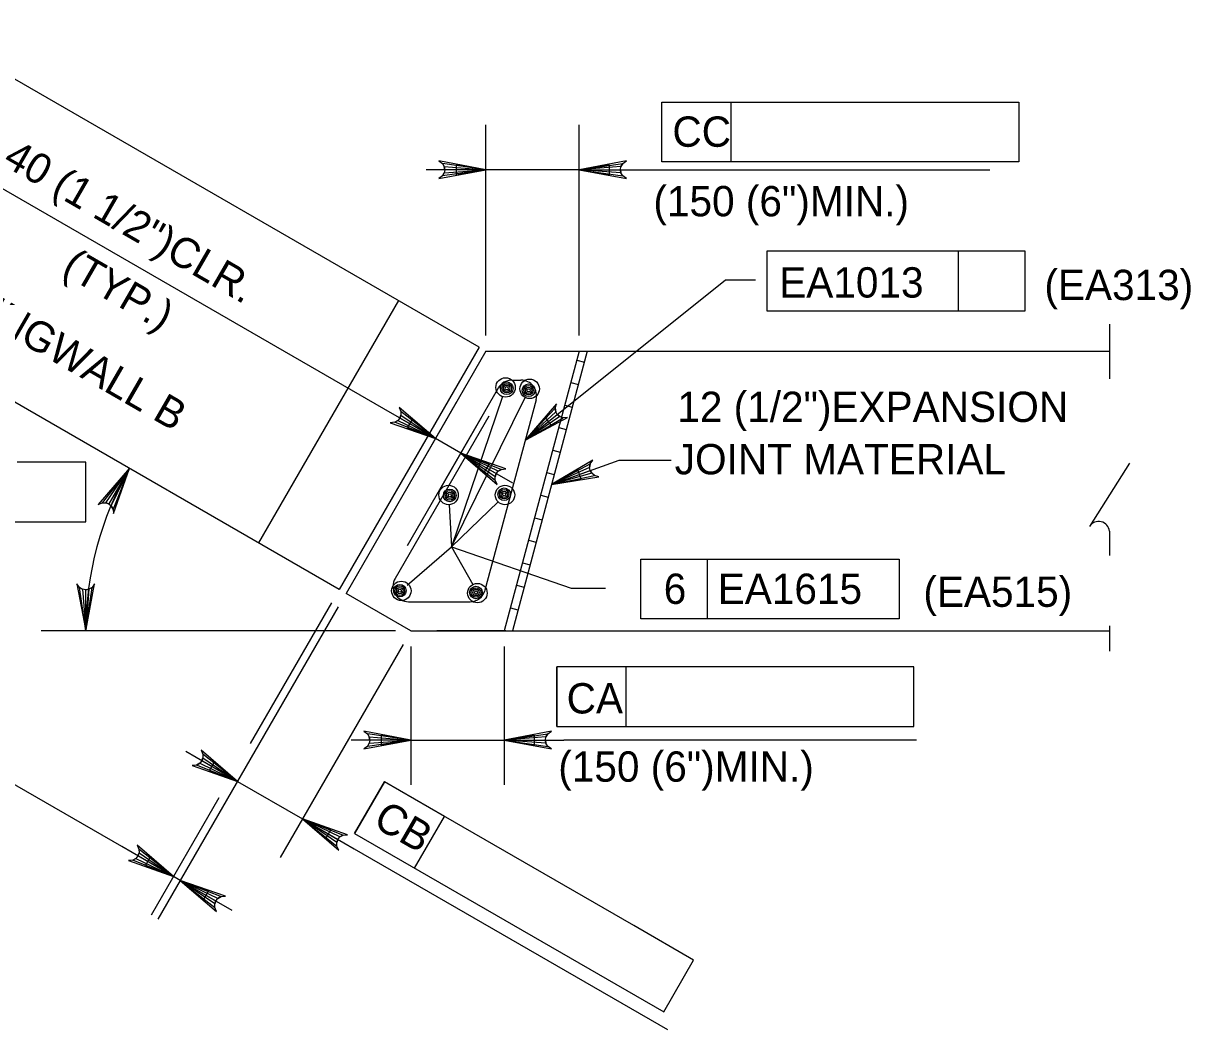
# Model space of a CAD drawing. Extents: x 638340 to 640241, y 295465 to 298435.
# Drawn here: x 638568.5 to 638683.9, y 296941.4 to 297041 of the extents above; entities that cross this region are included whole.
import ezdxf

# ---------------------------------------------------------------- set-up
doc = ezdxf.new("R2010")
doc.units = 0
for name, color, linetype in [('10', 7, 'Continuous'), ('3', 7, 'Continuous'), ('4', 7, 'Continuous'), ('5', 7, 'Continuous')]:
    doc.layers.add(name, color=color, linetype=linetype)

msp = doc.modelspace()

# ---------------------------------------------------------------- linework, layer by layer
at = {"layer": '10'}
for p, q in [((638613.57, 297008.95), (638558.08, 297040.99)), ((638599.73, 296984.98), (638544.23, 297017.02)), ((638605.58, 297013.57), (638591.74, 296989.59)), ((638613.57, 297008.95), (638599.73, 296984.98)), ((638614.24, 297008.57), (638600.4, 296984.59)), ((638614.24, 297008.57), (638675.9, 297008.57)), ((638623.47, 297008.57), (638616.05, 296980.88)), ((638624.26, 297008.57), (638616.85, 296980.88)), ((638623.23, 297007.68), (638623.97, 297007.48)), ((638622.63, 297005.45), (638623.38, 297005.25)), ((638622.04, 297003.22), (638622.78, 297003.02)), ((638621.44, 297001), (638622.18, 297000.8)), ((638620.84, 296998.77), (638621.58, 296998.57)), ((638620.24, 296996.54), (638620.99, 296996.34)), ((638619.65, 296994.31), (638620.39, 296994.11)), ((638619.05, 296992.08), (638619.79, 296991.88)), ((638618.45, 296989.85), (638619.2, 296989.65)), ((638617.85, 296987.63), (638618.6, 296987.43)), ((638617.26, 296985.4), (638618, 296985.2)), ((638606.82, 296980.88), (638600.4, 296984.59)), ((638616.66, 296983.17), (638617.4, 296982.97)), ((638606.82, 296980.88), (638675.9, 296980.88)), ((638616.05, 296980.88), (638609.37, 296980.88)), ((638616.06, 296980.94), (638616.27, 296980.88))]:
    msp.add_line(p, q, dxfattribs=at)
at = {"layer": '3'}
for p, q in [((638631.64, 297033.21), (638638.48, 297033.21)), ((638631.64, 297027.3), (638631.64, 297033.21)), ((638638.48, 297027.3), (638638.48, 297033.21)), ((638638.48, 297033.21), (638666.94, 297033.21)), ((638666.94, 297033.21), (638666.94, 297027.3)), ((638614.24, 297010.11), (638614.24, 297030.94)), ((638623.47, 297010.11), (638623.47, 297030.94)), ((638611.29, 297026.51), (638608.34, 297026.51)), ((638623.47, 297026.51), (638614.24, 297026.51)), ((638626.42, 297026.51), (638664.07, 297026.51)), ((638666.94, 297027.3), (638631.64, 297027.3)), ((638604.13, 297002.86), (638565.91, 297024.93)), ((638667.57, 297018.46), (638642.03, 297018.46)), ((638642.03, 297018.46), (638642.03, 297012.56)), ((638660.98, 297012.56), (638660.98, 297018.46)), ((638667.57, 297012.56), (638667.57, 297018.46)), ((638618.12, 296999.76), (638637.94, 297015.61)), ((638637.94, 297015.61), (638640.89, 297015.61)), ((638642.03, 297012.56), (638667.57, 297012.56)), ((638611.29, 297003.47), (638607.03, 296996.08)), ((638615.87, 297004.06), (638610.84, 296989.2)), ((638610.84, 296989.2), (638618.13, 297003.97)), ((638609.24, 296999.91), (638604.13, 297002.86)), ((638613.79, 297002.02), (638609.53, 296994.63)), ((638611.74, 296998.47), (638609.24, 296999.91)), ((638574.68, 296997.56), (638567.86, 296997.56)), ((638574.68, 296991.66), (638574.68, 296997.56)), ((638611.74, 296998.47), (638616.85, 296995.52)), ((638620.72, 296995.36), (638627.41, 296997.78)), ((638627.41, 296997.78), (638632.56, 296997.78)), ((638610.59, 296993.37), (638610.84, 296989.2)), ((638610.84, 296989.2), (638615.43, 296993.66)), ((638578.22, 296959.54), (638521.61, 296992.22)), ((638539.38, 296991.66), (638574.68, 296991.66)), ((638606.44, 296985.41), (638610.84, 296989.2)), ((638610.84, 296989.2), (638622.66, 296985.12)), ((638610.84, 296989.2), (638612.93, 296985.46)), ((638629.56, 296987.97), (638655.1, 296987.97)), ((638629.56, 296982.07), (638629.56, 296987.97)), ((638636.15, 296982.07), (638636.15, 296987.97)), ((638655.1, 296987.97), (638655.1, 296982.07)), ((638622.66, 296985.12), (638626.07, 296985.12)), ((638598.96, 296983.65), (638590.93, 296969.73)), ((638599.63, 296983.26), (638581.79, 296952.36)), ((638655.1, 296982.07), (638629.56, 296982.07)), ((638605.28, 296980.88), (638570.23, 296980.88)), ((638606.05, 296979.55), (638593.87, 296958.45)), ((638606.82, 296979.35), (638606.82, 296965.65)), ((638616.05, 296979.35), (638616.05, 296965.65)), ((638621.25, 296977.32), (638621.25, 296971.41)), ((638649.71, 296977.32), (638621.25, 296977.32)), ((638628.1, 296977.32), (638621.25, 296977.32)), ((638621.25, 296971.41), (638621.25, 296977.32)), ((638628.1, 296971.41), (638628.1, 296977.32)), ((638656.55, 296977.32), (638649.71, 296977.32)), ((638656.55, 296971.41), (638656.55, 296977.32)), ((638621.25, 296971.41), (638656.55, 296971.41)), ((638603.87, 296970.08), (638600.92, 296970.08)), ((638606.82, 296970.08), (638616.05, 296970.08)), ((638619, 296970.08), (638621.95, 296970.08)), ((638656.81, 296970.08), (638621.95, 296970.08)), ((638589.66, 296965.99), (638584.54, 296968.94)), ((638589.66, 296965.99), (638596.08, 296962.28)), ((638604.2, 296965.95), (638601.25, 296960.84)), ((638601.25, 296960.84), (638604.2, 296965.95)), ((638628.85, 296951.72), (638604.2, 296965.95)), ((638610.13, 296962.53), (638604.2, 296965.95)), ((638587.83, 296964.36), (638581.12, 296952.75)), ((638596.08, 296962.28), (638601.19, 296959.33)), ((638607.18, 296957.41), (638610.13, 296962.53)), ((638601.25, 296960.84), (638631.82, 296943.18)), ((638583.34, 296956.59), (638578.22, 296959.54)), ((638601.19, 296959.33), (638632.2, 296941.43)), ((638584, 296956.2), (638583.34, 296956.58)), ((638584, 296956.2), (638589.12, 296953.25)), ((638634.78, 296948.3), (638628.85, 296951.72)), ((638631.82, 296943.18), (638634.78, 296948.3))]:
    msp.add_line(p, q, dxfattribs=at)
for points in [[(638614.24, 297026.51), (638609.58, 297027.38), (638609.94, 297027.14), (638610.12, 297026.82), (638610.18, 297026.51), (638610.12, 297026.2), (638609.94, 297025.89), (638609.58, 297025.64), (638614.24, 297026.51), (638609.94, 297025.89), (638610.12, 297026.2), (638614.24, 297026.51), (638610.18, 297026.51), (638610.12, 297026.82), (638614.24, 297026.51), (638609.94, 297027.14)], [(638623.47, 297026.51), (638628.13, 297025.64), (638627.77, 297025.89), (638627.58, 297026.2), (638627.53, 297026.51), (638627.58, 297026.82), (638627.77, 297027.14), (638628.13, 297027.38), (638623.47, 297026.51), (638627.77, 297027.14), (638627.58, 297026.82), (638623.47, 297026.51), (638627.53, 297026.51), (638627.58, 297026.2), (638623.47, 297026.51), (638627.77, 297025.89)], [(638618.12, 296999.76), (638622.3, 297001.99), (638621.87, 297001.95), (638621.53, 297002.08), (638621.29, 297002.29), (638621.14, 297002.57), (638621.09, 297002.93), (638621.21, 297003.35), (638618.12, 296999.76), (638621.09, 297002.93), (638621.14, 297002.57), (638618.12, 296999.76), (638621.29, 297002.29), (638621.53, 297002.08), (638618.12, 296999.76), (638621.87, 297001.95)], [(638609.24, 296999.91), (638605.64, 297003), (638605.83, 297002.6), (638605.83, 297002.24), (638605.72, 297001.94), (638605.52, 297001.7), (638605.21, 297001.52), (638604.77, 297001.48), (638609.24, 296999.91), (638605.21, 297001.52), (638605.52, 297001.7), (638609.24, 296999.91), (638605.72, 297001.94), (638605.83, 297002.24), (638609.24, 296999.91), (638605.83, 297002.6)], [(638611.74, 296998.47), (638615.34, 296995.38), (638615.15, 296995.78), (638615.15, 296996.14), (638615.26, 296996.44), (638615.46, 296996.68), (638615.78, 296996.86), (638616.21, 296996.9), (638611.74, 296998.47), (638615.78, 296996.86), (638615.46, 296996.68), (638611.74, 296998.47), (638615.26, 296996.44), (638615.15, 296996.14), (638611.74, 296998.47), (638615.15, 296995.78)], [(638620.72, 296995.36), (638625.4, 296996.13), (638624.98, 296996.24), (638624.7, 296996.47), (638624.54, 296996.74), (638624.49, 296997.06), (638624.55, 296997.41), (638624.8, 296997.77), (638620.72, 296995.36), (638624.55, 296997.41), (638624.49, 296997.06), (638620.72, 296995.36), (638624.54, 296996.74), (638624.7, 296996.47), (638620.72, 296995.36), (638624.98, 296996.24)], [(638578.97, 296996.97), (638575.88, 296993.37), (638576.28, 296993.55), (638576.64, 296993.56), (638576.94, 296993.45), (638577.18, 296993.25), (638577.36, 296992.93), (638577.39, 296992.49), (638578.97, 296996.97), (638577.36, 296992.93), (638577.18, 296993.25), (638578.97, 296996.97), (638576.94, 296993.45), (638576.64, 296993.56), (638578.97, 296996.97), (638576.28, 296993.55)], [(638574.66, 296980.88), (638575.53, 296985.54), (638575.28, 296985.19), (638574.97, 296985), (638574.66, 296984.95), (638574.34, 296985), (638574.03, 296985.19), (638573.78, 296985.54), (638574.66, 296980.88), (638574.03, 296985.19), (638574.34, 296985), (638574.66, 296980.88), (638574.66, 296984.95), (638574.97, 296985), (638574.66, 296980.88), (638575.28, 296985.19)], [(638606.82, 296970.08), (638602.16, 296970.95), (638602.52, 296970.7), (638602.7, 296970.39), (638602.76, 296970.08), (638602.7, 296969.77), (638602.52, 296969.45), (638602.16, 296969.21), (638606.82, 296970.08), (638602.52, 296969.45), (638602.7, 296969.77), (638606.82, 296970.08), (638602.76, 296970.08), (638602.7, 296970.39), (638606.82, 296970.08), (638602.52, 296970.7)], [(638616.05, 296970.08), (638620.71, 296969.21), (638620.35, 296969.45), (638620.17, 296969.77), (638620.11, 296970.08), (638620.17, 296970.39), (638620.35, 296970.7), (638620.71, 296970.95), (638616.05, 296970.08), (638620.35, 296970.7), (638620.17, 296970.39), (638616.05, 296970.08), (638620.11, 296970.08), (638620.17, 296969.77), (638616.05, 296970.08), (638620.35, 296969.45)], [(638589.66, 296965.99), (638586.06, 296969.08), (638586.24, 296968.68), (638586.25, 296968.32), (638586.14, 296968.02), (638585.93, 296967.78), (638585.62, 296967.6), (638585.18, 296967.56), (638589.66, 296965.99), (638585.62, 296967.6), (638585.93, 296967.78), (638589.66, 296965.99), (638586.14, 296968.02), (638586.25, 296968.32), (638589.66, 296965.99), (638586.24, 296968.68)], [(638596.08, 296962.28), (638599.68, 296959.19), (638599.49, 296959.59), (638599.49, 296959.95), (638599.6, 296960.25), (638599.8, 296960.49), (638600.12, 296960.67), (638600.55, 296960.71), (638596.08, 296962.28), (638600.12, 296960.67), (638599.8, 296960.49), (638596.08, 296962.28), (638599.6, 296960.25), (638599.49, 296959.95), (638596.08, 296962.28), (638599.49, 296959.59)], [(638583.34, 296956.59), (638579.74, 296959.67), (638579.92, 296959.27), (638579.93, 296958.91), (638579.82, 296958.61), (638579.62, 296958.37), (638579.3, 296958.19), (638578.87, 296958.16), (638583.34, 296956.59), (638579.3, 296958.19), (638579.62, 296958.37), (638583.34, 296956.59), (638579.82, 296958.61), (638579.93, 296958.91), (638583.34, 296956.59), (638579.92, 296959.27)], [(638584, 296956.2), (638587.6, 296953.11), (638587.42, 296953.51), (638587.41, 296953.87), (638587.52, 296954.17), (638587.72, 296954.41), (638588.04, 296954.59), (638588.48, 296954.63), (638584, 296956.2), (638588.04, 296954.59), (638587.72, 296954.41), (638584, 296956.2), (638587.52, 296954.17), (638587.41, 296953.87), (638584, 296956.2), (638587.42, 296953.51)]]:
    msp.add_lwpolyline(points, dxfattribs=at)
for points in [[(638611.29, 297027), (638611.29, 297026.02), (638614.24, 297026.51)], [(638626.42, 297027), (638626.42, 297026.02), (638623.47, 297026.51)], [(638620.73, 297001.21), (638620.12, 297001.98), (638618.12, 296999.75)], [(638606.93, 297001.81), (638606.44, 297000.96), (638609.24, 296999.91)], [(638614.54, 296997.42), (638614.05, 296996.57), (638611.74, 296998.47)], [(638623.67, 296995.9), (638623.33, 296996.83), (638620.72, 296995.36)], [(638603.87, 296970.57), (638603.87, 296969.59), (638606.82, 296970.08)], [(638619, 296970.57), (638619, 296969.59), (638616.05, 296970.08)], [(638587.34, 296967.89), (638586.85, 296967.04), (638589.66, 296965.99)], [(638598.88, 296961.23), (638598.39, 296960.38), (638596.08, 296962.28)], [(638581.03, 296958.49), (638580.53, 296957.63), (638583.34, 296956.58)], [(638586.81, 296955.15), (638586.31, 296954.3), (638584, 296956.2)]]:
    msp.add_lwpolyline(points, close=True, dxfattribs=at)
for centre in [(638616.18, 297004.97), (638618.56, 297004.83), (638610.54, 296994.33), (638616.12, 296994.33), (638605.87, 296984.84), (638613.39, 296984.62)]:
    msp.add_circle(centre, 0.962, dxfattribs=at)
msp.add_arc((638606.82, 296980.88), 32.16, 149.9998, 180.0004, dxfattribs=at)
at = {"layer": '4'}
for p, q in [((638675.9, 297011.24), (638675.9, 297005.83)), ((638677.89, 296997.49), (638673.94, 296991.21)), ((638675.9, 296990.74), (638675.9, 296988.35)), ((638675.9, 296981.37), (638675.9, 296978.87))]:
    msp.add_line(p, q, dxfattribs=at)
msp.add_arc((638674.84, 296990.64), 1.07, 5.3286, 147.8672, dxfattribs=at)
at = {"layer": '5'}
for p, q in [((638616.79, 297005.68), (638617.7, 297005.68)), ((638615.46, 297004.91), (638606.44, 296989.29)), ((638619.19, 297003.75), (638614.14, 296984.91)), ((638614.53, 297002.14), (638605.25, 296986.08)), ((638606.58, 296983.77), (638612.66, 296983.77))]:
    msp.add_line(p, q, dxfattribs=at)
for centre, radius in [((638616.29, 297004.89), 0.625), ((638616.29, 297004.89), 0.469), ((638616.29, 297004.89), 0.313), ((638616.29, 297004.89), 0.156), ((638618.45, 297004.69), 0.625), ((638618.45, 297004.69), 0.469), ((638618.45, 297004.69), 0.313), ((638618.45, 297004.69), 0.156), ((638616.04, 296994.4), 0.625), ((638610.66, 296994.29), 0.625), ((638610.66, 296994.29), 0.469), ((638610.66, 296994.29), 0.313), ((638610.66, 296994.29), 0.156), ((638616.04, 296994.4), 0.469), ((638616.04, 296994.4), 0.313), ((638616.04, 296994.4), 0.156), ((638605.72, 296984.86), 0.625), ((638605.72, 296984.86), 0.469), ((638605.72, 296984.86), 0.313), ((638605.72, 296984.86), 0.156), ((638613.25, 296984.68), 0.625), ((638613.25, 296984.68), 0.469), ((638613.25, 296984.68), 0.313), ((638613.25, 296984.68), 0.156)]:
    msp.add_circle(centre, radius, dxfattribs=at)
for centre, start, end in [((638616.79, 297004.15), 90, 150), ((638617.7, 297004.15), 345, 90), ((638606.58, 296985.31), 150, 270), ((638612.66, 296985.31), 270, 345)]:
    msp.add_arc(centre, 1.54, start, end, dxfattribs=at)

# ---------------------------------------------------------------- texts
at = {"layer": '3'}
for s, height, p in [('CC', 3, (638632.68, 297028.78)), ('(150 (6")MIN.)', 3.0001, (638630.8, 297021.9)), ('EA1013', 3, (638643.24, 297013.86)), ('(EA313)', 3, (638669.47, 297013.61)), ('12 (1/2")EXPANSION', 3.0001, (638633.16, 297001.55)), ('JOINT MATERIAL', 3.0001, (638632.91, 296996.37)), ('6', 3, (638631.82, 296983.55)), ('EA1615', 3, (638637.16, 296983.55)), ('(EA515)', 3, (638657.5, 296983.26)), ('CA', 3, (638622.22, 296972.71)), ('(150 (6")MIN.)', 3.0001, (638621.39, 296965.96))]:
    msp.add_text(s, height=height, dxfattribs=at).set_placement(p)
for s, height, p in [(' 40 (1 1/2")CLR.', 3.0001, (638565.35, 297027.59)), ('(TYP.)', 3, (638572.15, 297016.27)), ('WINGWALL B', 3, (638561.25, 297013.39)), ('CB', 3, (638602.93, 296961.62))]:
    msp.add_text(s, height=height, rotation=330, dxfattribs=at).set_placement(p)

doc.saveas('drawing.dxf')
